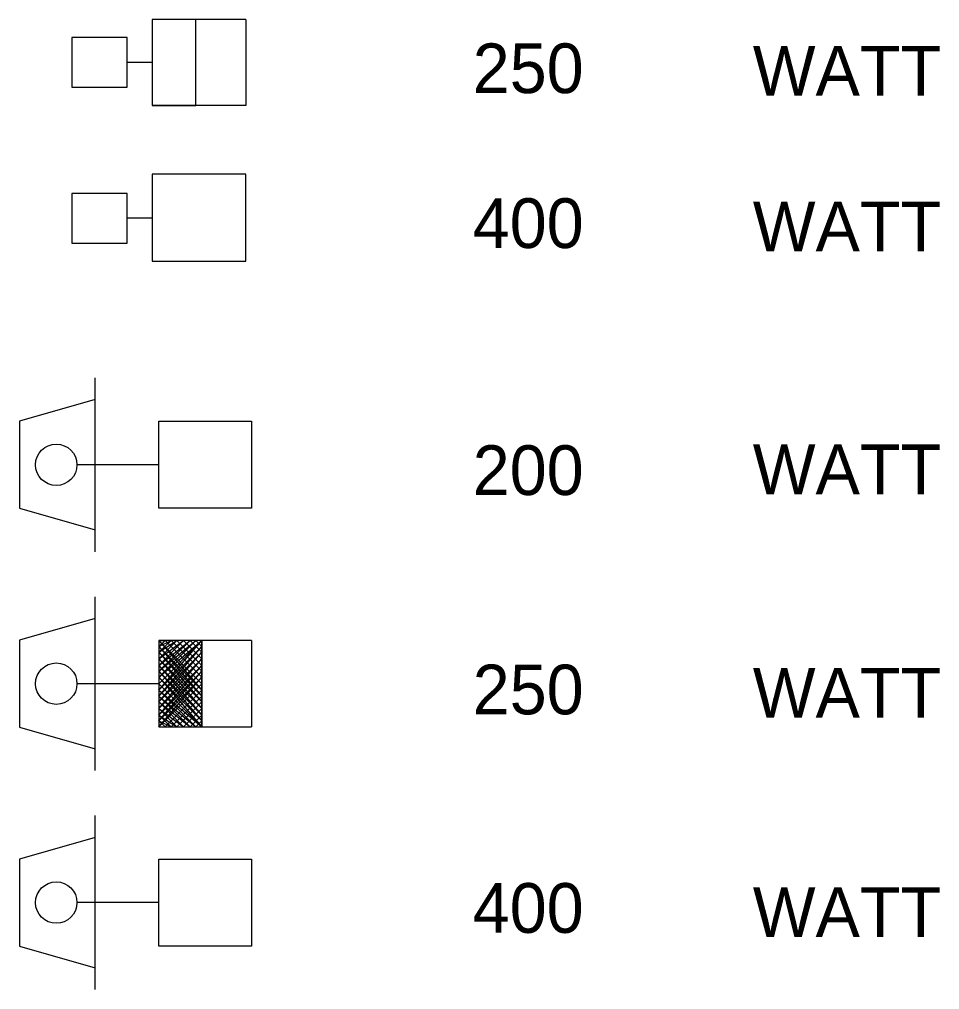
# Model space of a CAD drawing. Extents: x 10019.5 to 10026.1, y 9984.8 to 9994.8.
# Drawn here: x 10019.512 to 10020.622, y 9989.763 to 9990.935 of the extents above; entities that cross this region are included whole.
import ezdxf

# ---------------------------------------------------------------- set-up
doc = ezdxf.new("R2010")
doc.units = 0
doc.layers.add('DETL-LINE', color=7, linetype='Continuous')
doc.layers.add('DETL-NOTE', color=7, linetype='Continuous')

msp = doc.modelspace()

# ---------------------------------------------------------------- linework, layer by layer
at = {"layer": 'DETL-LINE'}
for p, q in [((10019.725, 9990.9347), (10019.672, 9990.9347)), ((10019.672, 9990.9347), (10019.672, 9990.8307)), ((10019.785, 9990.9347), (10019.725, 9990.9347)), ((10019.725, 9990.8307), (10019.725, 9990.9347)), ((10019.725, 9990.9347), (10019.725, 9990.9347)), ((10019.785, 9990.9347), (10019.785, 9990.8307)), ((10019.672, 9990.8827), (10019.642, 9990.8827)), ((10019.785, 9990.8307), (10019.672, 9990.8307)), ((10019.672, 9990.8307), (10019.725, 9990.8307)), ((10019.725, 9990.7477), (10019.672, 9990.7477)), ((10019.672, 9990.7477), (10019.672, 9990.6427)), ((10019.725, 9990.7477), (10019.725, 9990.7477)), ((10019.785, 9990.7477), (10019.725, 9990.7477)), ((10019.785, 9990.6427), (10019.785, 9990.7477)), ((10019.672, 9990.6947), (10019.642, 9990.6947)), ((10019.672, 9990.6427), (10019.785, 9990.6427)), ((10019.6032, 9990.4495), (10019.6032, 9990.502)), ((10019.6032, 9990.4758), (10019.5119, 9990.4495)), ((10019.5119, 9990.4495), (10019.5119, 9990.3445)), ((10019.6032, 9990.3445), (10019.6032, 9990.4495)), ((10019.68, 9990.4495), (10019.792, 9990.4495)), ((10019.68, 9990.3445), (10019.68, 9990.4495)), ((10019.792, 9990.4495), (10019.792, 9990.3445)), ((10019.6032, 9990.397), (10019.5814, 9990.397)), ((10019.68, 9990.397), (10019.6032, 9990.397)), ((10019.5119, 9990.3445), (10019.6032, 9990.3183)), ((10019.6032, 9990.292), (10019.6032, 9990.3445)), ((10019.792, 9990.3445), (10019.68, 9990.3445)), ((10019.6032, 9990.1852), (10019.6032, 9990.2377)), ((10019.6032, 9990.2115), (10019.5119, 9990.1852)), ((10019.5119, 9990.1852), (10019.5119, 9990.0802)), ((10019.6032, 9990.0802), (10019.6032, 9990.1852)), ((10019.68, 9990.1847), (10019.68, 9990.0807)), ((10019.68, 9990.1847), (10019.68, 9990.0807)), ((10019.68, 9990.1847), (10019.68, 9990.0807)), ((10019.68, 9990.1847), (10019.68, 9990.0807)), ((10019.68, 9990.1847), (10019.68, 9990.0807)), ((10019.732, 9990.1847), (10019.68, 9990.1847)), ((10019.68, 9990.1847), (10019.68, 9990.0807)), ((10019.68, 9990.1847), (10019.68, 9990.1847)), ((10019.68, 9990.1847), (10019.68, 9990.1847)), ((10019.68, 9990.1847), (10019.68, 9990.1847)), ((10019.68, 9990.1847), (10019.688, 9990.1847)), ((10019.68, 9990.1847), (10019.688, 9990.1847)), ((10019.68, 9990.1777), (10019.688, 9990.1847)), ((10019.68, 9990.1777), (10019.688, 9990.1847)), ((10019.68, 9990.1777), (10019.688, 9990.1847)), ((10019.68, 9990.1777), (10019.688, 9990.1847)), ((10019.68, 9990.1777), (10019.688, 9990.1847)), ((10019.68, 9990.1777), (10019.695, 9990.1847)), ((10019.68, 9990.1777), (10019.695, 9990.1847)), ((10019.68, 9990.1707), (10019.695, 9990.1847)), ((10019.68, 9990.1707), (10019.695, 9990.1847)), ((10019.68, 9990.1707), (10019.695, 9990.1847)), ((10019.68, 9990.1707), (10019.695, 9990.1847)), ((10019.68, 9990.1707), (10019.695, 9990.1847)), ((10019.68, 9990.1707), (10019.702, 9990.1847)), ((10019.68, 9990.1707), (10019.702, 9990.1847)), ((10019.68, 9990.1627), (10019.702, 9990.1847)), ((10019.68, 9990.1627), (10019.702, 9990.1847)), ((10019.68, 9990.1627), (10019.702, 9990.1847)), ((10019.68, 9990.1627), (10019.702, 9990.1847)), ((10019.68, 9990.1627), (10019.702, 9990.1847)), ((10019.68, 9990.1627), (10019.71, 9990.1847)), ((10019.68, 9990.1627), (10019.71, 9990.1847)), ((10019.68, 9990.1547), (10019.71, 9990.1847)), ((10019.68, 9990.1547), (10019.71, 9990.1847)), ((10019.68, 9990.1547), (10019.71, 9990.1847)), ((10019.68, 9990.1547), (10019.71, 9990.1847)), ((10019.68, 9990.1547), (10019.71, 9990.1847)), ((10019.68, 9990.1547), (10019.718, 9990.1847)), ((10019.68, 9990.1477), (10019.718, 9990.1847)), ((10019.68, 9990.1477), (10019.718, 9990.1847)), ((10019.68, 9990.1477), (10019.718, 9990.1847)), ((10019.68, 9990.1477), (10019.718, 9990.1847)), ((10019.68, 9990.1477), (10019.718, 9990.1847)), ((10019.68, 9990.1477), (10019.725, 9990.1847)), ((10019.68, 9990.1477), (10019.725, 9990.1847)), ((10019.68, 9990.1407), (10019.725, 9990.1847)), ((10019.68, 9990.1407), (10019.725, 9990.1847)), ((10019.68, 9990.1407), (10019.725, 9990.1847)), ((10019.68, 9990.1407), (10019.725, 9990.1847)), ((10019.68, 9990.1407), (10019.725, 9990.1847)), ((10019.68, 9990.1407), (10019.732, 9990.1847)), ((10019.68, 9990.1407), (10019.732, 9990.1847)), ((10019.68, 9990.1327), (10019.732, 9990.1847)), ((10019.68, 9990.1327), (10019.732, 9990.1847)), ((10019.68, 9990.1327), (10019.732, 9990.1847)), ((10019.68, 9990.1327), (10019.732, 9990.1847)), ((10019.68, 9990.1327), (10019.732, 9990.1847)), ((10019.68, 9990.1327), (10019.732, 9990.1847)), ((10019.68, 9990.1327), (10019.732, 9990.1847)), ((10019.68, 9990.1247), (10019.732, 9990.1847)), ((10019.68, 9990.1247), (10019.732, 9990.1847)), ((10019.68, 9990.1847), (10019.732, 9990.1327)), ((10019.68, 9990.1847), (10019.732, 9990.1327)), ((10019.68, 9990.1847), (10019.732, 9990.1327)), ((10019.68, 9990.1847), (10019.732, 9990.1327)), ((10019.68, 9990.1847), (10019.732, 9990.1327)), ((10019.68, 9990.1847), (10019.732, 9990.1327)), ((10019.68, 9990.1847), (10019.732, 9990.1327)), ((10019.68, 9990.1847), (10019.732, 9990.1247)), ((10019.68, 9990.1847), (10019.732, 9990.1247)), ((10019.688, 9990.1847), (10019.732, 9990.1407)), ((10019.688, 9990.1847), (10019.732, 9990.1407)), ((10019.688, 9990.1847), (10019.732, 9990.1407)), ((10019.688, 9990.1847), (10019.732, 9990.1407)), ((10019.688, 9990.1847), (10019.732, 9990.1407)), ((10019.688, 9990.1847), (10019.732, 9990.1407)), ((10019.688, 9990.1847), (10019.732, 9990.1407)), ((10019.695, 9990.1847), (10019.732, 9990.1477)), ((10019.695, 9990.1847), (10019.732, 9990.1477)), ((10019.695, 9990.1847), (10019.732, 9990.1477)), ((10019.695, 9990.1847), (10019.732, 9990.1477)), ((10019.695, 9990.1847), (10019.732, 9990.1477)), ((10019.695, 9990.1847), (10019.732, 9990.1477)), ((10019.695, 9990.1847), (10019.732, 9990.1477)), ((10019.702, 9990.1847), (10019.732, 9990.1547)), ((10019.702, 9990.1847), (10019.732, 9990.1547)), ((10019.702, 9990.1847), (10019.732, 9990.1547)), ((10019.702, 9990.1847), (10019.732, 9990.1547)), ((10019.702, 9990.1847), (10019.732, 9990.1547)), ((10019.702, 9990.1847), (10019.732, 9990.1547)), ((10019.71, 9990.1847), (10019.732, 9990.1627)), ((10019.71, 9990.1847), (10019.732, 9990.1627)), ((10019.71, 9990.1847), (10019.732, 9990.1627)), ((10019.71, 9990.1847), (10019.732, 9990.1627)), ((10019.71, 9990.1847), (10019.732, 9990.1627)), ((10019.71, 9990.1847), (10019.732, 9990.1627)), ((10019.71, 9990.1847), (10019.732, 9990.1627)), ((10019.718, 9990.1847), (10019.732, 9990.1707)), ((10019.718, 9990.1847), (10019.732, 9990.1707)), ((10019.718, 9990.1847), (10019.732, 9990.1707)), ((10019.718, 9990.1847), (10019.732, 9990.1707)), ((10019.718, 9990.1847), (10019.732, 9990.1707)), ((10019.718, 9990.1847), (10019.732, 9990.1707)), ((10019.725, 9990.1847), (10019.732, 9990.1777)), ((10019.725, 9990.1847), (10019.732, 9990.1777)), ((10019.725, 9990.1847), (10019.732, 9990.1777)), ((10019.725, 9990.1847), (10019.732, 9990.1777)), ((10019.725, 9990.1847), (10019.732, 9990.1777)), ((10019.725, 9990.1847), (10019.732, 9990.1777)), ((10019.725, 9990.1847), (10019.732, 9990.1777)), ((10019.725, 9990.1847), (10019.732, 9990.1777)), ((10019.792, 9990.1847), (10019.732, 9990.1847)), ((10019.732, 9990.1847), (10019.732, 9990.0807)), ((10019.732, 9990.0807), (10019.732, 9990.1847)), ((10019.732, 9990.0807), (10019.732, 9990.1847)), ((10019.732, 9990.1847), (10019.732, 9990.0807)), ((10019.732, 9990.0807), (10019.732, 9990.1847)), ((10019.732, 9990.0807), (10019.732, 9990.1847)), ((10019.732, 9990.0807), (10019.732, 9990.1847)), ((10019.732, 9990.1847), (10019.732, 9990.1847)), ((10019.732, 9990.1847), (10019.732, 9990.1847)), ((10019.732, 9990.1847), (10019.732, 9990.1847)), ((10019.732, 9990.1847), (10019.732, 9990.1847)), ((10019.732, 9990.1847), (10019.732, 9990.1847)), ((10019.792, 9990.1847), (10019.792, 9990.0807)), ((10019.68, 9990.1247), (10019.732, 9990.1777)), ((10019.68, 9990.1247), (10019.732, 9990.1777)), ((10019.68, 9990.1247), (10019.732, 9990.1777)), ((10019.68, 9990.1247), (10019.732, 9990.1777)), ((10019.68, 9990.1247), (10019.732, 9990.1777)), ((10019.68, 9990.1177), (10019.732, 9990.1777)), ((10019.68, 9990.1177), (10019.732, 9990.1777)), ((10019.68, 9990.1777), (10019.732, 9990.1247)), ((10019.68, 9990.1777), (10019.732, 9990.1247)), ((10019.68, 9990.1777), (10019.732, 9990.1247)), ((10019.68, 9990.1777), (10019.732, 9990.1247)), ((10019.68, 9990.1777), (10019.732, 9990.1247)), ((10019.68, 9990.1777), (10019.732, 9990.1177)), ((10019.68, 9990.1777), (10019.732, 9990.1177)), ((10019.68, 9990.1177), (10019.732, 9990.1707)), ((10019.68, 9990.1177), (10019.732, 9990.1707)), ((10019.68, 9990.1177), (10019.732, 9990.1707)), ((10019.68, 9990.1177), (10019.732, 9990.1707)), ((10019.68, 9990.1177), (10019.732, 9990.1707)), ((10019.68, 9990.1107), (10019.732, 9990.1707)), ((10019.68, 9990.1707), (10019.732, 9990.1177)), ((10019.68, 9990.1707), (10019.732, 9990.1177)), ((10019.68, 9990.1707), (10019.732, 9990.1177)), ((10019.68, 9990.1707), (10019.732, 9990.1177)), ((10019.68, 9990.1707), (10019.732, 9990.1177)), ((10019.68, 9990.1707), (10019.732, 9990.1107)), ((10019.68, 9990.1107), (10019.732, 9990.1627)), ((10019.68, 9990.1107), (10019.732, 9990.1627)), ((10019.68, 9990.1107), (10019.732, 9990.1627)), ((10019.68, 9990.1107), (10019.732, 9990.1627)), ((10019.68, 9990.1107), (10019.732, 9990.1627)), ((10019.68, 9990.1027), (10019.732, 9990.1627)), ((10019.68, 9990.1027), (10019.732, 9990.1627)), ((10019.68, 9990.1627), (10019.732, 9990.1107)), ((10019.68, 9990.1627), (10019.732, 9990.1107)), ((10019.68, 9990.1627), (10019.732, 9990.1107)), ((10019.68, 9990.1627), (10019.732, 9990.1107)), ((10019.68, 9990.1627), (10019.732, 9990.1107)), ((10019.68, 9990.1627), (10019.732, 9990.1027)), ((10019.68, 9990.1627), (10019.732, 9990.1027)), ((10019.68, 9990.1027), (10019.732, 9990.1547)), ((10019.68, 9990.1027), (10019.732, 9990.1547)), ((10019.68, 9990.1027), (10019.732, 9990.1547)), ((10019.68, 9990.1027), (10019.732, 9990.1547)), ((10019.68, 9990.1027), (10019.732, 9990.1547)), ((10019.68, 9990.0947), (10019.732, 9990.1547)), ((10019.68, 9990.0947), (10019.732, 9990.1547)), ((10019.68, 9990.1547), (10019.732, 9990.1027)), ((10019.68, 9990.1547), (10019.732, 9990.1027)), ((10019.68, 9990.1547), (10019.732, 9990.1027)), ((10019.68, 9990.1547), (10019.732, 9990.1027)), ((10019.68, 9990.1547), (10019.732, 9990.1027)), ((10019.68, 9990.1547), (10019.732, 9990.0947)), ((10019.68, 9990.1547), (10019.732, 9990.0947)), ((10019.68, 9990.0947), (10019.732, 9990.1477)), ((10019.68, 9990.0947), (10019.732, 9990.1477)), ((10019.68, 9990.0947), (10019.732, 9990.1477)), ((10019.68, 9990.0947), (10019.732, 9990.1477)), ((10019.68, 9990.0877), (10019.732, 9990.1477)), ((10019.68, 9990.0877), (10019.732, 9990.1477)), ((10019.68, 9990.0877), (10019.732, 9990.1477)), ((10019.68, 9990.1477), (10019.732, 9990.0947)), ((10019.68, 9990.1477), (10019.732, 9990.0947)), ((10019.68, 9990.1477), (10019.732, 9990.0947)), ((10019.68, 9990.1477), (10019.732, 9990.0947)), ((10019.68, 9990.1477), (10019.732, 9990.0947)), ((10019.68, 9990.1477), (10019.732, 9990.0877)), ((10019.68, 9990.1477), (10019.732, 9990.0877)), ((10019.68, 9990.0877), (10019.732, 9990.1407)), ((10019.68, 9990.0877), (10019.732, 9990.1407)), ((10019.68, 9990.0877), (10019.732, 9990.1407)), ((10019.68, 9990.0877), (10019.732, 9990.1407)), ((10019.68, 9990.0877), (10019.732, 9990.1407)), ((10019.68, 9990.0807), (10019.732, 9990.1407)), ((10019.68, 9990.0807), (10019.732, 9990.1407)), ((10019.68, 9990.1407), (10019.732, 9990.0877)), ((10019.68, 9990.1407), (10019.732, 9990.0877)), ((10019.68, 9990.1407), (10019.732, 9990.0877)), ((10019.68, 9990.1407), (10019.732, 9990.0877)), ((10019.68, 9990.1407), (10019.732, 9990.0877)), ((10019.68, 9990.1407), (10019.732, 9990.0807)), ((10019.68, 9990.1407), (10019.732, 9990.0807)), ((10019.6032, 9990.1327), (10019.5814, 9990.1327)), ((10019.68, 9990.1327), (10019.6032, 9990.1327)), ((10019.68, 9990.0807), (10019.732, 9990.1327)), ((10019.68, 9990.0807), (10019.732, 9990.1327)), ((10019.68, 9990.0807), (10019.732, 9990.1327)), ((10019.68, 9990.0807), (10019.732, 9990.1327)), ((10019.68, 9990.0807), (10019.732, 9990.1327)), ((10019.68, 9990.0807), (10019.732, 9990.1327)), ((10019.68, 9990.1327), (10019.732, 9990.0807)), ((10019.68, 9990.1327), (10019.732, 9990.0807)), ((10019.68, 9990.1327), (10019.732, 9990.0807)), ((10019.68, 9990.1327), (10019.732, 9990.0807)), ((10019.68, 9990.1327), (10019.732, 9990.0807)), ((10019.68, 9990.1327), (10019.732, 9990.0807)), ((10019.68, 9990.1247), (10019.732, 9990.0807)), ((10019.68, 9990.1247), (10019.732, 9990.0807)), ((10019.68, 9990.1247), (10019.725, 9990.0807)), ((10019.68, 9990.1247), (10019.725, 9990.0807)), ((10019.68, 9990.1247), (10019.725, 9990.0807)), ((10019.68, 9990.1247), (10019.725, 9990.0807)), ((10019.68, 9990.1247), (10019.725, 9990.0807)), ((10019.688, 9990.0807), (10019.732, 9990.1247)), ((10019.688, 9990.0807), (10019.732, 9990.1247)), ((10019.688, 9990.0807), (10019.732, 9990.1247)), ((10019.688, 9990.0807), (10019.732, 9990.1247)), ((10019.688, 9990.0807), (10019.732, 9990.1247)), ((10019.688, 9990.0807), (10019.732, 9990.1247)), ((10019.688, 9990.0807), (10019.732, 9990.1247)), ((10019.68, 9990.1177), (10019.725, 9990.0807)), ((10019.68, 9990.1177), (10019.725, 9990.0807)), ((10019.68, 9990.1177), (10019.725, 9990.0807)), ((10019.68, 9990.1177), (10019.718, 9990.0807)), ((10019.68, 9990.1177), (10019.718, 9990.0807)), ((10019.68, 9990.1177), (10019.718, 9990.0807)), ((10019.68, 9990.1177), (10019.718, 9990.0807)), ((10019.695, 9990.0807), (10019.732, 9990.1177)), ((10019.695, 9990.0807), (10019.732, 9990.1177)), ((10019.695, 9990.0807), (10019.732, 9990.1177)), ((10019.695, 9990.0807), (10019.732, 9990.1177)), ((10019.695, 9990.0807), (10019.732, 9990.1177)), ((10019.695, 9990.0807), (10019.732, 9990.1177)), ((10019.695, 9990.0807), (10019.732, 9990.1177)), ((10019.68, 9990.1107), (10019.718, 9990.0807)), ((10019.68, 9990.1107), (10019.718, 9990.0807)), ((10019.68, 9990.1107), (10019.71, 9990.0807)), ((10019.68, 9990.1107), (10019.71, 9990.0807)), ((10019.68, 9990.1107), (10019.71, 9990.0807)), ((10019.68, 9990.1107), (10019.71, 9990.0807)), ((10019.68, 9990.1107), (10019.71, 9990.0807)), ((10019.68, 9990.1027), (10019.71, 9990.0807)), ((10019.68, 9990.1027), (10019.71, 9990.0807)), ((10019.68, 9990.1027), (10019.702, 9990.0807)), ((10019.68, 9990.1027), (10019.702, 9990.0807)), ((10019.68, 9990.1027), (10019.702, 9990.0807)), ((10019.68, 9990.1027), (10019.702, 9990.0807)), ((10019.68, 9990.1027), (10019.702, 9990.0807)), ((10019.702, 9990.0807), (10019.732, 9990.1107)), ((10019.702, 9990.0807), (10019.732, 9990.1107)), ((10019.702, 9990.0807), (10019.732, 9990.1107)), ((10019.702, 9990.0807), (10019.732, 9990.1107)), ((10019.702, 9990.0807), (10019.732, 9990.1107)), ((10019.702, 9990.0807), (10019.732, 9990.1107)), ((10019.702, 9990.0807), (10019.732, 9990.1107)), ((10019.71, 9990.0807), (10019.732, 9990.1027)), ((10019.71, 9990.0807), (10019.732, 9990.1027)), ((10019.71, 9990.0807), (10019.732, 9990.1027)), ((10019.71, 9990.0807), (10019.732, 9990.1027)), ((10019.71, 9990.0807), (10019.732, 9990.1027)), ((10019.71, 9990.0807), (10019.732, 9990.1027)), ((10019.71, 9990.0807), (10019.732, 9990.1027)), ((10019.68, 9990.0947), (10019.702, 9990.0807)), ((10019.68, 9990.0947), (10019.695, 9990.0807)), ((10019.68, 9990.0947), (10019.695, 9990.0807)), ((10019.68, 9990.0947), (10019.695, 9990.0807)), ((10019.68, 9990.0947), (10019.695, 9990.0807)), ((10019.68, 9990.0947), (10019.695, 9990.0807)), ((10019.718, 9990.0807), (10019.732, 9990.0947)), ((10019.718, 9990.0807), (10019.732, 9990.0947)), ((10019.718, 9990.0807), (10019.732, 9990.0947)), ((10019.718, 9990.0807), (10019.732, 9990.0947)), ((10019.718, 9990.0807), (10019.732, 9990.0947)), ((10019.718, 9990.0807), (10019.732, 9990.0947)), ((10019.5119, 9990.0802), (10019.6032, 9990.054)), ((10019.6032, 9990.0277), (10019.6032, 9990.0802)), ((10019.68, 9990.0877), (10019.695, 9990.0807)), ((10019.68, 9990.0877), (10019.695, 9990.0807)), ((10019.68, 9990.0877), (10019.688, 9990.0807)), ((10019.68, 9990.0877), (10019.688, 9990.0807)), ((10019.68, 9990.0877), (10019.688, 9990.0807)), ((10019.68, 9990.0877), (10019.688, 9990.0807)), ((10019.68, 9990.0877), (10019.688, 9990.0807)), ((10019.68, 9990.0807), (10019.732, 9990.0807)), ((10019.68, 9990.0807), (10019.688, 9990.0807)), ((10019.68, 9990.0807), (10019.688, 9990.0807)), ((10019.68, 9990.0807), (10019.68, 9990.0807)), ((10019.68, 9990.0807), (10019.68, 9990.0807)), ((10019.68, 9990.0807), (10019.68, 9990.0807)), ((10019.68, 9990.0807), (10019.68, 9990.0807)), ((10019.725, 9990.0807), (10019.732, 9990.0877)), ((10019.725, 9990.0807), (10019.732, 9990.0877)), ((10019.725, 9990.0807), (10019.732, 9990.0877)), ((10019.725, 9990.0807), (10019.732, 9990.0877)), ((10019.725, 9990.0807), (10019.732, 9990.0877)), ((10019.725, 9990.0807), (10019.732, 9990.0877)), ((10019.725, 9990.0807), (10019.732, 9990.0877)), ((10019.732, 9990.0807), (10019.792, 9990.0807)), ((10019.732, 9990.0807), (10019.732, 9990.0807)), ((10019.732, 9990.0807), (10019.732, 9990.0807)), ((10019.732, 9990.0807), (10019.732, 9990.0807)), ((10019.732, 9990.0807), (10019.732, 9990.0807)), ((10019.732, 9990.0807), (10019.732, 9990.0807)), ((10019.6032, 9989.9209), (10019.6032, 9989.9734)), ((10019.6032, 9989.9471), (10019.5119, 9989.9209)), ((10019.5119, 9989.9209), (10019.5119, 9989.8159)), ((10019.6032, 9989.8159), (10019.6032, 9989.9209)), ((10019.6032, 9989.8684), (10019.5814, 9989.8684)), ((10019.68, 9989.8684), (10019.6032, 9989.8684)), ((10019.5119, 9989.8159), (10019.6032, 9989.7896)), ((10019.6032, 9989.7634), (10019.6032, 9989.8159))]:
    msp.add_line(p, q, dxfattribs=at)
for points in [[(10019.575, 9990.8527), (10019.642, 9990.8527), (10019.642, 9990.9127), (10019.575, 9990.9127)], [(10019.575, 9990.6647), (10019.642, 9990.6647), (10019.642, 9990.7247), (10019.575, 9990.7247)], [(10019.68, 9989.9209), (10019.792, 9989.9209), (10019.792, 9989.8159), (10019.68, 9989.8159)]]:
    msp.add_lwpolyline(points, close=True, dxfattribs=at)
for centre in [(10019.5564, 9990.397), (10019.5564, 9990.1327), (10019.5564, 9989.8684)]:
    msp.add_circle(centre, 0.025, dxfattribs=at)

# ---------------------------------------------------------------- texts
at = {"layer": 'DETL-NOTE'}
for s, p in [('250', (10020.059, 9990.8457)), ('WATT', (10020.397, 9990.8427)), ('400', (10020.059, 9990.6587)), ('WATT', (10020.397, 9990.6547)), ('200', (10020.059, 9990.3605)), ('WATT', (10020.397, 9990.3615)), ('250', (10020.059, 9990.0957)), ('WATT', (10020.397, 9990.0917)), ('400', (10020.059, 9989.8319)), ('WATT', (10020.397, 9989.8269))]:
    msp.add_text(s, height=0.06, dxfattribs=at).set_placement(p)

doc.saveas('drawing.dxf')
